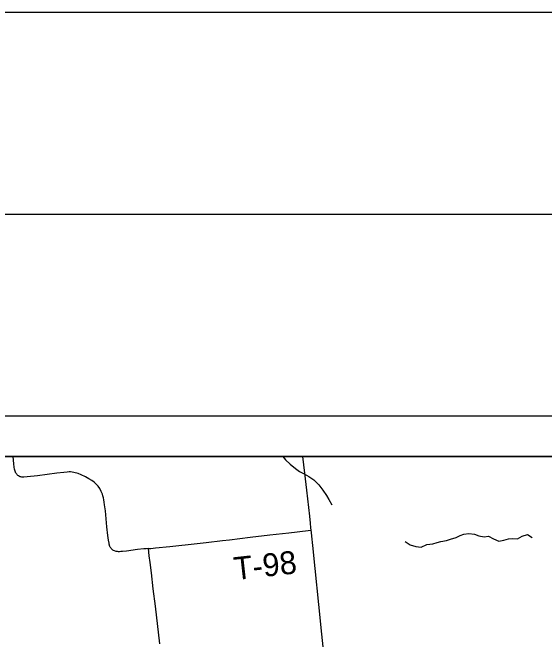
# Model space of a CAD drawing. Extents: x 0 to 34, y -5.4 to 22.
# Drawn here: x 3.798 to 5.117, y 20.446 to 22 of the extents above; entities that cross this region are included whole.
import ezdxf

# ---------------------------------------------------------------- set-up
doc = ezdxf.new("R2010")
doc.units = 0
for name, color, linetype in [('GM_X_County_Road', 7, 'Continuous'), ('GM_X_Minor_River', 7, 'Continuous'), ('GM_X_Rail_Line', 7, 'Continuous'), ('GM_X_Township_Road', 7, 'Continuous'), ('GM_X_Township_Road_Text', 7, 'Continuous'), ('SH_Border', 7, 'Continuous'), ('SH_Cut_Line', 7, 'Continuous'), ('SH_Data', 7, 'Continuous')]:
    doc.layers.add(name, color=color, linetype=linetype)

msp = doc.modelspace()

# ---------------------------------------------------------------- linework, layer by layer
at = {"layer": 'GM_X_County_Road'}
for points in [[(3.8053, 20.8599), (3.8049, 20.8608), (3.8041, 20.8629), (3.8034, 20.8654), (3.8029, 20.868), (3.8021, 20.8734), (3.8011, 20.8813), (3.799, 20.9)], [(4.6127, 20.0058), (4.6112, 20.0202), (4.6084, 20.0472), (4.604, 20.0905), (4.5963, 20.1653), (4.5953, 20.1744), (4.5946, 20.1819), (4.5913, 20.2128), (4.5856, 20.2647), (4.5812, 20.3042), (4.5747, 20.3641), (4.5646, 20.4593), (4.5568, 20.5328), (4.5477, 20.6224), (4.5419, 20.6793), (4.5398, 20.7021), (4.5389, 20.7111), (4.5382, 20.7168), (4.5376, 20.723), (4.5365, 20.7343), (4.5346, 20.7517), (4.5271, 20.8165), (4.5224, 20.8584), (4.5177, 20.9)], [(4.1346, 20.6713), (4.1292, 20.6711), (4.1236, 20.6706), (4.1076, 20.6689), (4.0806, 20.6653), (4.0703, 20.6641), (4.0663, 20.6638), (4.0627, 20.6636), (4.0603, 20.6636), (4.0577, 20.6638), (4.0549, 20.6642), (4.0508, 20.6654), (4.0482, 20.6666), (4.0465, 20.6675), (4.0453, 20.6686), (4.0436, 20.67), (4.0424, 20.6716), (4.041, 20.6733), (4.0401, 20.6751), (4.0392, 20.6769), (4.0384, 20.6789), (4.0379, 20.6803), (4.0375, 20.6818), (4.0371, 20.6834), (4.0369, 20.6848), (4.0358, 20.6919), (4.0349, 20.6978), (4.0342, 20.7041), (4.0318, 20.7255), (4.0278, 20.7652), (4.026, 20.78), (4.0251, 20.7867), (4.0241, 20.7922), (4.023, 20.7971), (4.0218, 20.802), (4.0204, 20.8061), (4.0177, 20.8132), (4.0143, 20.8199), (4.01, 20.8261), (4.0053, 20.8313), (4, 20.8358), (3.9939, 20.8402), (3.987, 20.8445), (3.9783, 20.8494), (3.9681, 20.8543), (3.9605, 20.8572), (3.9568, 20.8587), (3.9533, 20.8595), (3.9495, 20.8603), (3.9452, 20.861), (3.9416, 20.8613), (3.9377, 20.8612), (3.9328, 20.8609), (3.9245, 20.8601), (3.9079, 20.858), (3.8598, 20.8518), (3.8339, 20.8488), (3.8259, 20.8482), (3.8223, 20.8484), (3.8205, 20.8486), (3.8185, 20.849), (3.8165, 20.8496), (3.8146, 20.8503), (3.8128, 20.8514), (3.8109, 20.8527), (3.8095, 20.854), (3.808, 20.8555), (3.8069, 20.8571), (3.8056, 20.859), (3.8053, 20.8599)], [(4.1631, 20.4356), (4.152, 20.5288), (4.1465, 20.572), (4.142, 20.6109), (4.1389, 20.637), (4.1368, 20.6533), (4.1346, 20.6713)]]:
    msp.add_lwpolyline(points, dxfattribs=at)
at = {"layer": 'GM_X_Minor_River'}
for points in [[(4.4683, 20.9), (4.4742, 20.8916), (4.4858, 20.8808), (4.4989, 20.8696), (4.509, 20.8626), (4.5211, 20.8563), (4.5327, 20.8501), (4.5451, 20.8415), (4.557, 20.8296), (4.5674, 20.8161), (4.5759, 20.8031), (4.5822, 20.7931), (4.5892, 20.7797)], [(4.7713, 20.6888), (4.7836, 20.681), (4.7976, 20.6763), (4.8105, 20.6749), (4.8253, 20.6815), (4.8401, 20.6832), (4.8504, 20.6865), (4.8599, 20.689), (4.874, 20.6918), (4.8839, 20.6943), (4.8976, 20.699), (4.9075, 20.7034), (4.9171, 20.7067), (4.9292, 20.7088), (4.9432, 20.707), (4.9541, 20.7027), (4.9674, 20.7006), (4.978, 20.7019), (4.99, 20.6953), (5.0032, 20.6898), (5.0161, 20.6922), (5.0272, 20.6955), (5.0366, 20.6965), (5.0499, 20.6955), (5.061, 20.7018), (5.0743, 20.7061), (5.0863, 20.6991)]]:
    msp.add_lwpolyline(points, dxfattribs=at)
at = {"layer": 'GM_X_Rail_Line'}
msp.add_lwpolyline([(8.9, 19.2127), (8.9, 20.9), (3.5133, 20.9), (3.5122, 20.8763), (3.4778, 20.1697), (3.46, 19.8188), (3.4303, 19.2337), (3.4301, 19.2311), (3.4297, 19.2264), (3.3865, 18.7781), (3.3669, 18.5872), (3.5131, 18.6037), (4.7505, 18.7432), (5.0255, 18.7742), (5.096, 18.7806), (5.378, 18.814), (5.7313, 18.8595), (5.7334, 18.8597), (6.0045, 18.8908), (6.4496, 18.9373), (6.6792, 18.9603), (6.9054, 18.9823), (7.2315, 19.0156), (8.5201, 19.1691)], close=True, dxfattribs=at)
at = {"layer": 'GM_X_Township_Road'}
msp.add_lwpolyline([(4.1346, 20.6713), (4.1403, 20.6719), (4.1525, 20.6732), (4.1873, 20.6767), (4.2558, 20.6841), (4.2774, 20.6865), (4.3181, 20.6915), (4.336, 20.6934), (4.3873, 20.6993), (4.4353, 20.7051), (4.4829, 20.7105), (4.5304, 20.716), (4.531, 20.7161), (4.5382, 20.7168)], dxfattribs=at)
at = {"layer": 'SH_Border'}
msp.add_lwpolyline([(1.5, 21.5), (33.5, 21.5), (33.5, 0.5), (1.5, 0.5)], close=True, dxfattribs=at)
at = {"layer": 'SH_Cut_Line'}
msp.add_lwpolyline([(0, 0), (34, 0), (34, 22), (0, 22)], close=True, dxfattribs=at)
at = {"layer": 'SH_Data'}
for p, q in [((2, 21), (9, 21)), ((2.1, 20.9), (8.9, 20.9))]:
    msp.add_line(p, q, dxfattribs=at)

# ---------------------------------------------------------------- texts
at = {"layer": 'GM_X_Township_Road_Text'}
msp.add_text('T-98', height=0.05682, rotation=6.3785, dxfattribs=at).set_placement((4.3495, 20.593))

doc.saveas('drawing.dxf')
